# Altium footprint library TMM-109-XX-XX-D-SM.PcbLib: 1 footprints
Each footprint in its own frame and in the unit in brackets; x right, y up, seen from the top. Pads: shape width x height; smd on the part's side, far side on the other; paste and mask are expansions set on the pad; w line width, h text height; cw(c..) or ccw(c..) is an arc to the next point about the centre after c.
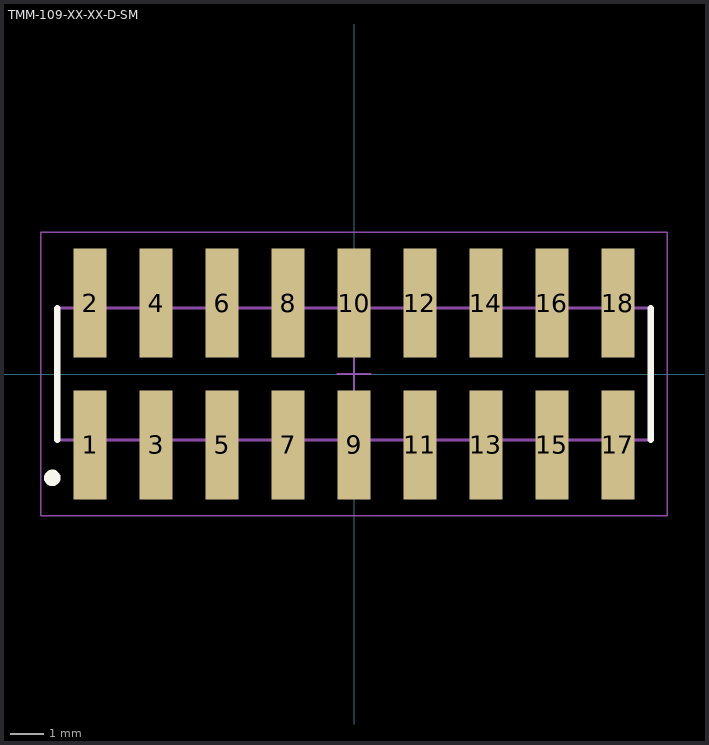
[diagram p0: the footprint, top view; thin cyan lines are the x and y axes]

## TMM-109-XX-XX-D-SM [mm] "2.00mm pitch, 18 pin, terminal strip; double row, SMT"
height 2.77
pads (18):
  rect 1x3.3 smd mask+0: 1(-8,-2.15) 2(-8,2.15) 3(-6,-2.15) 4(-6,2.15) 5(-4,-2.15) 6(-4,2.15) 7(-2,-2.15) 8(-2,2.15) 9(0,-2.15) 10(0,2.15) 11(2,-2.15) 12(2,2.15) 13(4,-2.15) 14(4,2.15) 15(6,-2.15) 16(6,2.15) 17(8,-2.15) 18(8,2.15)
Top Overlay:
  circle w0.25: c-9.15,-3.15 r0.125
  lines w0.2: -9,-2 -9,2 ; 9,-2 9,2
Mechanical 12:
  lines w0.001: -9,-2 9,-2 9,2 -9,2 -9,-2
Mechanical 13:
  lines w0.1: -9,-2 9,-2 9,2 -9,2 -9,-2
  text ".Designator" at 0,-0.127 h1.52
Mechanical 15:
  lines w0.05: -0.5,0 0.5,0 ; 0,-0.5 0,0.5 ; -9.5,-4.3 9.5,-4.3 9.5,4.3 -9.5,4.3 -9.5,-4.3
